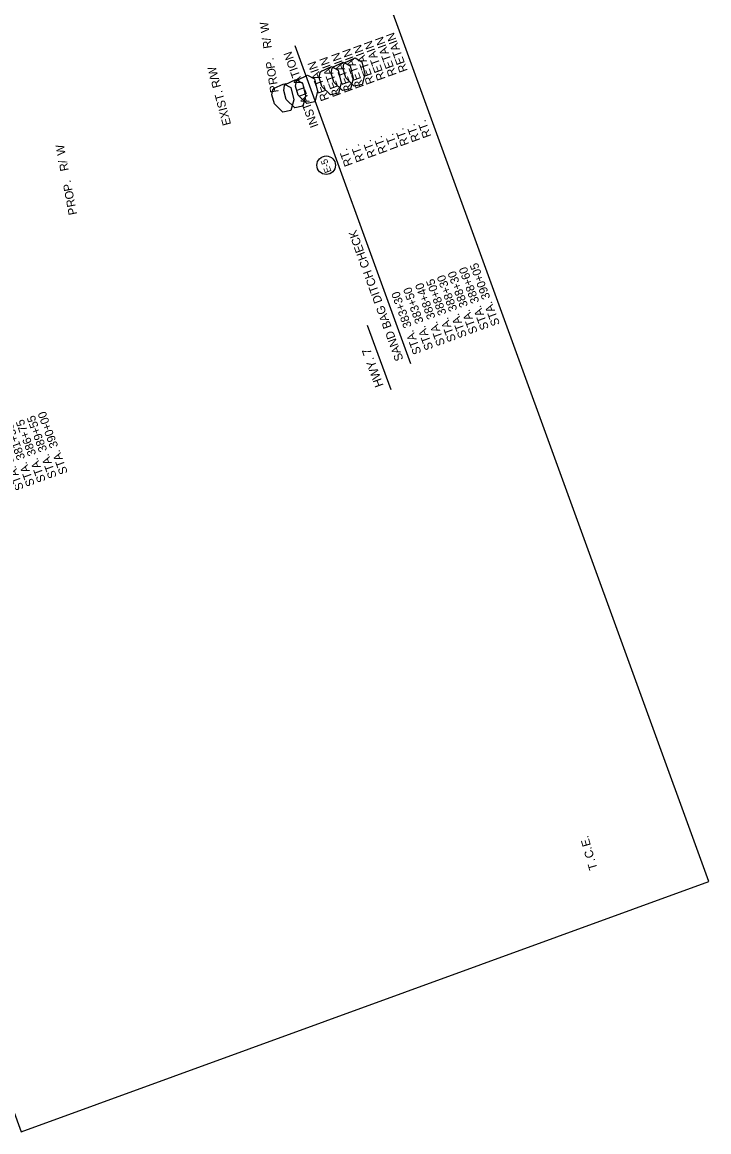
# Model space of a CAD drawing. Extents: x 960650 to 962115, y 1906452 to 1908757.
# Drawn here: x 961626 to 962115, y 1907079 to 1907870 of the extents above; entities that cross this region are included whole.
import ezdxf

# ---------------------------------------------------------------- set-up
doc = ezdxf.new("R2010")
doc.units = 0
for name, color, linetype in [('1', 7, 'Continuous'), ('44', 7, 'Continuous'), ('NO PLOT', 7, 'Continuous'), ('R_Draft', 7, 'Continuous'), ('S_TREE', 7, 'Continuous')]:
    doc.layers.add(name, color=color, linetype=linetype)

msp = doc.modelspace()

# ---------------------------------------------------------------- linework, layer by layer
at = {"layer": '1'}
msp.add_line((961859.67, 1907757.17), (961859.67, 1907757.17), dxfattribs=at)
msp.add_line((961859.67, 1907757.17), (961859.67, 1907757.17), dxfattribs=at)
msp.add_circle((961842.06, 1907767.83), 6.61, dxfattribs=at)
at = {"layer": '44'}
for p, q in [((961902.29, 1907626.4), (961819.86, 1907852.87)), ((961888.22, 1907607.78), (961871.51, 1907653.67))]:
    msp.add_line(p, q, dxfattribs=at)
at = {"layer": 'NO PLOT'}
msp.add_lwpolyline([(962114.55, 1907257.7), (961568.91, 1908756.85), (961079.18, 1908578.6), (961182.12, 1908295.76), (961245.55, 1908318.85), (961390.91, 1907919.48), (961327.48, 1907896.39), (961425.36, 1907627.47), (961483.4, 1907648.6), (961600.59, 1907326.6), (961542.56, 1907305.48), (961624.82, 1907079.46)], close=True, dxfattribs=at)
msp.add_lwpolyline([(962114.55, 1907257.7), (961568.91, 1908756.85), (961079.18, 1908578.6), (961182.12, 1908295.76), (961245.55, 1908318.85), (961390.91, 1907919.48), (961327.48, 1907896.39), (961425.36, 1907627.47), (961483.4, 1907648.6), (961600.59, 1907326.6), (961542.56, 1907305.48), (961624.82, 1907079.46)], close=True, dxfattribs=at)
msp.add_lwpolyline([(962114.55, 1907257.7), (961568.91, 1908756.85), (961079.18, 1908578.6), (961182.12, 1908295.76), (961245.55, 1908318.85), (961390.91, 1907919.48), (961327.48, 1907896.39), (961425.36, 1907627.47), (961483.4, 1907648.6), (961600.59, 1907326.6), (961542.56, 1907305.48), (961624.82, 1907079.46)], close=True, dxfattribs=at)
msp.add_lwpolyline([(962114.55, 1907257.7), (961568.91, 1908756.85), (961079.18, 1908578.6), (961182.12, 1908295.76), (961245.55, 1908318.85), (961390.91, 1907919.48), (961327.48, 1907896.39), (961425.36, 1907627.47), (961483.4, 1907648.6), (961600.59, 1907326.6), (961542.56, 1907305.48), (961624.82, 1907079.46)], close=True, dxfattribs=at)
msp.add_lwpolyline([(962114.55, 1907257.7), (961568.91, 1908756.85), (961079.18, 1908578.6), (961182.12, 1908295.76), (961245.55, 1908318.85), (961390.91, 1907919.48), (961327.48, 1907896.39), (961425.36, 1907627.47), (961483.4, 1907648.6), (961600.59, 1907326.6), (961542.56, 1907305.48), (961624.82, 1907079.46)], close=True, dxfattribs=at)
at = {"layer": 'S_TREE'}
for points in [[(961846.73, 1907837.75), (961854.21, 1907841.24), (961859.04, 1907838.51), (961861.19, 1907829.68), (961859.25, 1907822.3), (961853.55, 1907821.02), (961847.47, 1907826.91), (961845.61, 1907833.35), (961846.22, 1907837.01), (961847.42, 1907838.23)], [(961846.73, 1907837.75), (961854.21, 1907841.24), (961859.04, 1907838.51), (961861.19, 1907829.68), (961859.25, 1907822.3), (961853.55, 1907821.02), (961847.47, 1907826.91), (961845.61, 1907833.35), (961846.22, 1907837.01), (961847.42, 1907838.23)], [(961846.73, 1907837.75), (961854.21, 1907841.24), (961859.04, 1907838.51), (961861.19, 1907829.68), (961859.25, 1907822.3), (961853.55, 1907821.02), (961847.47, 1907826.91), (961845.61, 1907833.35), (961846.22, 1907837.01), (961847.42, 1907838.23)], [(961846.73, 1907837.75), (961854.21, 1907841.24), (961859.04, 1907838.51), (961861.19, 1907829.68), (961859.25, 1907822.3), (961853.55, 1907821.02), (961847.47, 1907826.91), (961845.61, 1907833.35), (961846.22, 1907837.01), (961847.42, 1907838.23)], [(961846.73, 1907837.75), (961854.21, 1907841.24), (961859.04, 1907838.51), (961861.19, 1907829.68), (961859.25, 1907822.3), (961853.55, 1907821.02), (961847.47, 1907826.91), (961845.61, 1907833.35), (961846.22, 1907837.01), (961847.42, 1907838.23)], [(961855.19, 1907840.83), (961862.66, 1907844.32), (961867.49, 1907841.58), (961869.64, 1907832.76), (961867.71, 1907825.37), (961862, 1907824.1), (961855.92, 1907829.99), (961854.07, 1907836.43), (961854.68, 1907840.09), (961855.87, 1907841.31)], [(961855.19, 1907840.83), (961862.66, 1907844.32), (961867.49, 1907841.58), (961869.64, 1907832.76), (961867.71, 1907825.37), (961862, 1907824.1), (961855.92, 1907829.99), (961854.07, 1907836.43), (961854.68, 1907840.09), (961855.87, 1907841.31)], [(961855.19, 1907840.83), (961862.66, 1907844.32), (961867.49, 1907841.58), (961869.64, 1907832.76), (961867.71, 1907825.37), (961862, 1907824.1), (961855.92, 1907829.99), (961854.07, 1907836.43), (961854.68, 1907840.09), (961855.87, 1907841.31)], [(961855.19, 1907840.83), (961862.66, 1907844.32), (961867.49, 1907841.58), (961869.64, 1907832.76), (961867.71, 1907825.37), (961862, 1907824.1), (961855.92, 1907829.99), (961854.07, 1907836.43), (961854.68, 1907840.09), (961855.87, 1907841.31)], [(961821.36, 1907828.52), (961828.84, 1907832.01), (961833.67, 1907829.27), (961835.81, 1907820.44), (961833.88, 1907813.06), (961828.18, 1907811.79), (961822.1, 1907817.67), (961820.24, 1907824.12), (961820.85, 1907827.77), (961822.04, 1907828.99)], [(961821.36, 1907828.52), (961828.84, 1907832.01), (961833.67, 1907829.27), (961835.81, 1907820.44), (961833.88, 1907813.06), (961828.18, 1907811.79), (961822.1, 1907817.67), (961820.24, 1907824.12), (961820.85, 1907827.77), (961822.04, 1907828.99)], [(961838.28, 1907834.68), (961845.75, 1907838.16), (961850.58, 1907835.43), (961852.73, 1907826.6), (961850.79, 1907819.22), (961845.09, 1907817.95), (961839.01, 1907823.83), (961837.15, 1907830.28), (961837.77, 1907833.93), (961838.96, 1907835.15)], [(961838.28, 1907834.68), (961845.75, 1907838.16), (961850.58, 1907835.43), (961852.73, 1907826.6), (961850.79, 1907819.22), (961845.09, 1907817.95), (961839.01, 1907823.83), (961837.15, 1907830.28), (961837.77, 1907833.93), (961838.96, 1907835.15)], [(961838.28, 1907834.68), (961845.75, 1907838.16), (961850.58, 1907835.43), (961852.73, 1907826.6), (961850.79, 1907819.22), (961845.09, 1907817.95), (961839.01, 1907823.83), (961837.15, 1907830.28), (961837.77, 1907833.93), (961838.96, 1907835.15)], [(961838.28, 1907834.68), (961845.75, 1907838.16), (961850.58, 1907835.43), (961852.73, 1907826.6), (961850.79, 1907819.22), (961845.09, 1907817.95), (961839.01, 1907823.83), (961837.15, 1907830.28), (961837.77, 1907833.93), (961838.96, 1907835.15)], [(961804.45, 1907822.36), (961811.92, 1907825.85), (961816.75, 1907823.11), (961818.9, 1907814.29), (961816.96, 1907806.91), (961811.26, 1907805.63), (961805.18, 1907811.52), (961803.32, 1907817.96), (961803.94, 1907821.62), (961805.13, 1907822.84)], [(961804.45, 1907822.36), (961811.92, 1907825.85), (961816.75, 1907823.11), (961818.9, 1907814.29), (961816.96, 1907806.91), (961811.26, 1907805.63), (961805.18, 1907811.52), (961803.32, 1907817.96), (961803.94, 1907821.62), (961805.13, 1907822.84)], [(961812.91, 1907825.44), (961820.38, 1907828.93), (961825.21, 1907826.19), (961827.36, 1907817.37), (961825.42, 1907809.98), (961819.72, 1907808.71), (961813.64, 1907814.6), (961811.78, 1907821.04), (961812.39, 1907824.7), (961813.59, 1907825.92)], [(961812.91, 1907825.44), (961820.38, 1907828.93), (961825.21, 1907826.19), (961827.36, 1907817.37), (961825.42, 1907809.98), (961819.72, 1907808.71), (961813.64, 1907814.6), (961811.78, 1907821.04), (961812.39, 1907824.7), (961813.59, 1907825.92)]]:
    msp.add_lwpolyline(points, dxfattribs=at)

# ---------------------------------------------------------------- texts
at = {"layer": '1'}
msp.add_text('E-5 ', height=4.8, rotation=110, dxfattribs=at).set_placement((961845.9, 1907763.37))
at = {"layer": '44'}
for s, height, p in [('RETAIN', 6, (961884.36, 1907829.47)), ('RETAIN', 6, (961892.34, 1907832.37)), ('RETAIN', 6, (961900.17, 1907835.22)), ('INSTALLATION', 6, (961836.63, 1907795.81)), ('RETAIN', 6, (961861.18, 1907821.03)), ('RETAIN', 6, (961869.01, 1907823.88)), ('RETAIN', 6, (961876.68, 1907826.67)), ('RETAIN', 6, (961844.26, 1907814.87)), ('RETAIN', 6, (961852.72, 1907817.95)), ('RT.', 6, (961916.98, 1907788.56)), ('RT.', 6, (961901.16, 1907782.81)), ('RT.', 6, (961909.15, 1907785.71)), ('RT.', 6, (961877.98, 1907774.37)), ('RT.', 6, (961885.81, 1907777.22)), ('LT.', 6, (961893.44, 1907780.15)), ('RT.', 6, (961861.07, 1907768.22)), ('RT.', 6, (961869.53, 1907771.29)), ('SAND BAG DITCH CHECK', 6, (961897.12, 1907629.62)), ('STA. 390+05', 6, (961965.88, 1907654.64)), ('STA. 388+30', 6, (961942.39, 1907646.09)), ('STA. 388+30', 6, (961950.06, 1907648.89)), ('STA. 388+60', 6, (961958.05, 1907651.79)), ('STA. 383+50', 6, (961918.43, 1907637.37)), ('STA. 388+40', 6, (961926.88, 1907640.45)), ('STA. 388+05', 6, (961934.71, 1907643.3)), ('STA. 383+30', 6, (961909.97, 1907634.29)), ('HWY. 7', 6.25, (961883.01, 1907611.04)), ('STA. 386+75', 6, (961642.47, 1907543.17)), ('STA. 389+55', 6, (961650.3, 1907546.02)), ('STA. 390+00', 6, (961658.13, 1907548.87)), ('STA. 378+45', 6, (961626.81, 1907537.47)), ('STA. 381+35', 6, (961634.64, 1907540.32))]:
    msp.add_text(s, height=height, rotation=110, dxfattribs=at).set_placement(p)
at = {"layer": 'R_Draft'}
for s, rotation, p in [('W', 98.68221, (961801.69, 1907862.78)), ('/', 98.68221, (961802.58, 1907856.99)), ('R', 98.68221, (961803.43, 1907851.39)), ('P', 98.68221, (961805.64, 1907836.96)), ('.', 98.68221, (961804.78, 1907842.56)), ('EXIST. R/W', 105.0127, (961774.37, 1907797.01)), ('O', 98.68221, (961806.52, 1907831.17)), ('R', 98.68221, (961807.38, 1907825.56)), ('P', 98.68221, (961808.23, 1907819.96)), ('W', 100.8503, (961656.53, 1907775.52)), ('/', 100.8503, (961657.63, 1907769.77)), ('R', 100.8503, (961658.7, 1907764.2)), ('P', 100.8503, (961661.45, 1907749.86)), ('.', 100.8503, (961660.38, 1907755.43)), ('O', 100.8503, (961662.55, 1907744.11)), ('R', 100.8503, (961663.62, 1907738.54)), ('P', 100.8503, (961664.68, 1907732.97)), ('E', 105.81657, (962030.6, 1907283.5)), ('.', 105.81657, (962029.13, 1907288.68)), ('C', 105.81657, (962032.94, 1907275.23)), ('.', 105.81657, (962031.4, 1907280.68)), ('T', 105.81657, (962035.34, 1907266.78)), ('.', 105.81657, (962033.74, 1907272.41))]:
    msp.add_text(s, height=6, rotation=rotation, dxfattribs=at).set_placement(p)

doc.saveas('drawing.dxf')
